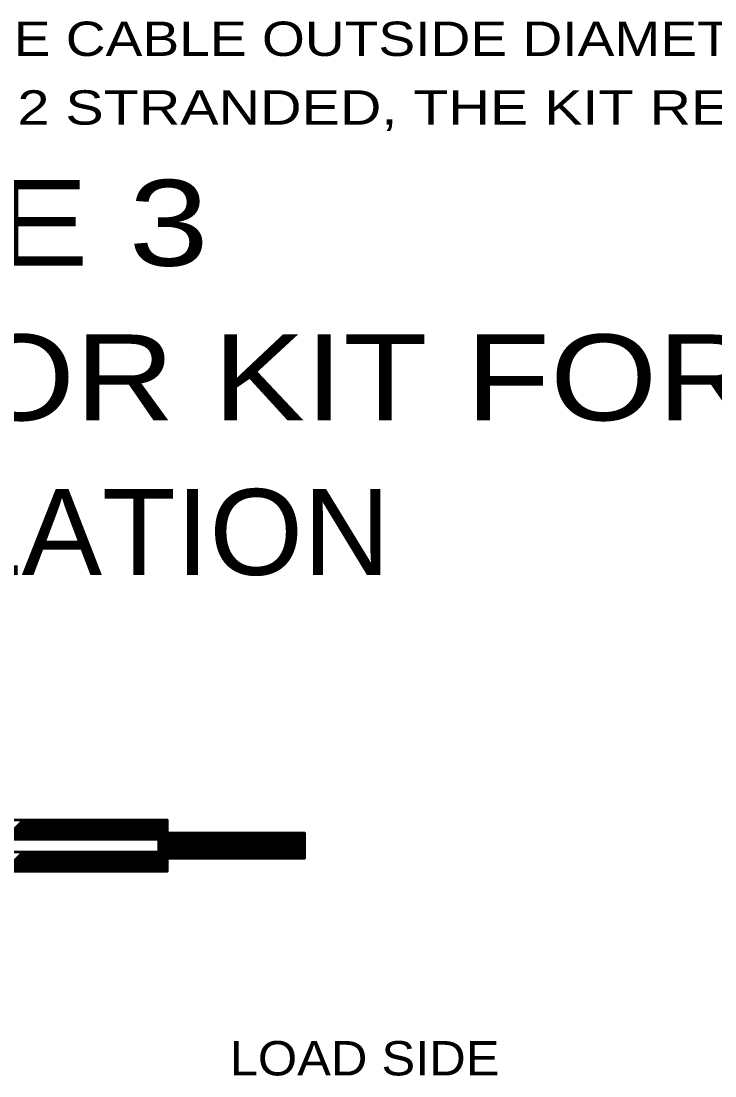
# Model space of a CAD drawing. Extents: x -32 to 824, y -6 to 538.
# Drawn here: x 656.1 to 704.6, y 268.2 to 341.9 of the extents above; entities that cross this region are included whole.
import ezdxf
from ezdxf.enums import TextEntityAlignment as Align

# ---------------------------------------------------------------- set-up
doc = ezdxf.new("R2010")
doc.units = 0
doc.header["$LTSCALE"] = 1.1
doc.layers.add('1', color=7, linetype='Continuous', lineweight=53)

msp = doc.modelspace()

# ---------------------------------------------------------------- linework, layer by layer
at = {"layer": '1'}
for p, q in [((654.939, 284.763), (656.289, 286.113)), ((655.109, 284.763), (656.459, 286.113)), ((655.279, 284.763), (656.629, 286.113)), ((655.448, 284.763), (656.798, 286.113)), ((655.618, 284.763), (656.968, 286.113)), ((655.788, 284.763), (657.138, 286.113)), ((655.957, 284.763), (657.307, 286.113)), ((656.127, 284.763), (657.477, 286.113)), ((656.297, 284.763), (657.647, 286.113)), ((656.466, 284.763), (657.817, 286.113)), ((656.636, 284.763), (657.986, 286.113)), ((656.806, 284.763), (658.156, 286.113)), ((656.976, 284.763), (658.326, 286.113)), ((657.145, 284.763), (658.495, 286.113)), ((657.315, 284.763), (658.665, 286.113)), ((657.485, 284.763), (658.835, 286.113)), ((657.654, 284.763), (659.004, 286.113)), ((657.824, 284.763), (659.174, 286.113)), ((657.994, 284.763), (659.344, 286.113)), ((658.163, 284.763), (659.514, 286.113)), ((658.333, 284.763), (659.683, 286.113)), ((658.503, 284.763), (659.853, 286.113)), ((658.673, 284.763), (660.023, 286.113)), ((658.842, 284.763), (660.192, 286.113)), ((659.012, 284.763), (660.362, 286.113)), ((659.182, 284.763), (660.532, 286.113)), ((659.351, 284.763), (660.702, 286.113)), ((659.521, 284.763), (660.871, 286.113)), ((659.691, 284.763), (661.041, 286.113)), ((659.861, 284.763), (661.211, 286.113)), ((660.03, 284.763), (661.38, 286.113)), ((660.2, 284.763), (661.55, 286.113)), ((660.37, 284.763), (661.72, 286.113)), ((660.539, 284.763), (661.889, 286.113)), ((660.709, 284.763), (662.059, 286.113)), ((660.879, 284.763), (662.229, 286.113)), ((661.048, 284.763), (662.399, 286.113)), ((661.218, 284.763), (662.568, 286.113)), ((661.388, 284.763), (662.738, 286.113)), ((661.558, 284.763), (662.908, 286.113)), ((661.727, 284.763), (663.077, 286.113)), ((661.897, 284.763), (663.247, 286.113)), ((662.067, 284.763), (663.417, 286.113)), ((662.236, 284.763), (663.587, 286.113)), ((662.406, 284.763), (663.756, 286.113)), ((662.576, 284.763), (663.926, 286.113)), ((662.746, 284.763), (664.096, 286.113)), ((662.915, 284.763), (664.265, 286.113)), ((663.085, 284.763), (664.435, 286.113)), ((663.255, 284.763), (664.605, 286.113)), ((663.424, 284.763), (664.774, 286.113)), ((663.594, 284.763), (664.944, 286.113)), ((663.764, 284.763), (665.114, 286.113)), ((663.933, 284.763), (665.284, 286.113)), ((664.103, 284.763), (665.453, 286.113)), ((664.273, 284.763), (665.623, 286.113)), ((664.443, 284.763), (665.793, 286.113)), ((664.612, 284.763), (665.962, 286.113)), ((664.782, 284.763), (666.132, 286.113)), ((664.952, 284.763), (666.302, 286.113)), ((665.122, 284.763), (666.32, 285.961)), ((665.291, 284.763), (666.32, 285.791)), ((665.461, 284.763), (666.32, 285.622)), ((665.631, 284.763), (666.32, 285.452)), ((665.72, 284.683), (666.32, 285.282)), ((665.72, 284.513), (666.32, 285.113)), ((665.72, 284.343), (666.32, 284.943)), ((665.72, 284.174), (666.32, 284.773)), ((665.72, 284.004), (666.32, 284.603)), ((666.32, 285.17), (666.363, 285.213)), ((666.32, 285), (666.533, 285.213)), ((666.32, 284.83), (666.702, 285.213)), ((666.32, 284.661), (666.872, 285.213)), ((666.32, 284.491), (667.042, 285.213)), ((666.32, 284.321), (667.211, 285.213)), ((666.32, 284.151), (667.381, 285.213)), ((666.32, 283.982), (667.551, 285.213)), ((666.32, 283.812), (667.721, 285.213)), ((666.32, 283.642), (667.89, 285.213)), ((666.32, 283.473), (668.06, 285.213)), ((668.054, 283.413), (666.32, 285.146)), ((667.884, 283.413), (666.32, 284.977)), ((667.714, 283.413), (666.32, 284.807)), ((667.545, 283.413), (666.32, 284.637)), ((668.223, 283.413), (666.423, 285.213)), ((666.43, 283.413), (668.23, 285.213)), ((668.393, 283.413), (666.593, 285.213)), ((666.599, 283.413), (668.399, 285.213)), ((668.563, 283.413), (666.763, 285.213)), ((666.769, 283.413), (668.569, 285.213)), ((668.732, 283.413), (666.932, 285.213)), ((666.939, 283.413), (668.739, 285.213)), ((668.902, 283.413), (667.102, 285.213)), ((667.109, 283.413), (668.909, 285.213)), ((669.072, 283.413), (667.272, 285.213)), ((667.278, 283.413), (669.078, 285.213)), ((669.242, 283.413), (667.442, 285.213)), ((667.448, 283.413), (669.248, 285.213)), ((669.411, 283.413), (667.611, 285.213)), ((667.618, 283.413), (669.418, 285.213)), ((669.581, 283.413), (667.781, 285.213)), ((667.787, 283.413), (669.587, 285.213)), ((669.751, 283.413), (667.951, 285.213)), ((667.957, 283.413), (669.757, 285.213)), ((669.92, 283.413), (668.12, 285.213)), ((668.127, 283.413), (669.927, 285.213)), ((670.09, 283.413), (668.29, 285.213)), ((668.296, 283.413), (670.096, 285.213)), ((670.26, 283.413), (668.46, 285.213)), ((668.466, 283.413), (670.266, 285.213)), ((670.43, 283.413), (668.63, 285.213)), ((668.636, 283.413), (670.436, 285.213)), ((670.599, 283.413), (668.799, 285.213)), ((668.806, 283.413), (670.606, 285.213)), ((670.769, 283.413), (668.969, 285.213)), ((668.975, 283.413), (670.775, 285.213)), ((670.939, 283.413), (669.139, 285.213)), ((669.145, 283.413), (670.945, 285.213)), ((671.108, 283.413), (669.308, 285.213)), ((669.315, 283.413), (671.115, 285.213)), ((671.278, 283.413), (669.478, 285.213)), ((669.484, 283.413), (671.284, 285.213)), ((671.448, 283.413), (669.648, 285.213)), ((669.654, 283.413), (671.454, 285.213)), ((671.617, 283.413), (669.817, 285.213)), ((669.824, 283.413), (671.624, 285.213)), ((671.787, 283.413), (669.987, 285.213)), ((669.994, 283.413), (671.793, 285.213)), ((671.957, 283.413), (670.157, 285.213)), ((670.163, 283.413), (671.963, 285.213)), ((672.127, 283.413), (670.327, 285.213)), ((670.333, 283.413), (672.133, 285.213)), ((672.296, 283.413), (670.496, 285.213)), ((670.503, 283.413), (672.303, 285.213)), ((672.466, 283.413), (670.666, 285.213)), ((670.672, 283.413), (672.472, 285.213)), ((672.636, 283.413), (670.836, 285.213)), ((670.842, 283.413), (672.642, 285.213)), ((672.805, 283.413), (671.005, 285.213)), ((671.012, 283.413), (672.812, 285.213)), ((672.975, 283.413), (671.175, 285.213)), ((671.181, 283.413), (672.981, 285.213)), ((673.145, 283.413), (671.345, 285.213)), ((671.351, 283.413), (673.151, 285.213)), ((673.315, 283.413), (671.514, 285.213)), ((671.521, 283.413), (673.321, 285.213)), ((673.484, 283.413), (671.684, 285.213)), ((671.691, 283.413), (673.49, 285.213)), ((673.654, 283.413), (671.854, 285.213)), ((671.86, 283.413), (673.66, 285.213)), ((673.824, 283.413), (672.024, 285.213)), ((672.03, 283.413), (673.83, 285.213)), ((673.993, 283.413), (672.193, 285.213)), ((672.2, 283.413), (674, 285.213)), ((674.163, 283.413), (672.363, 285.213)), ((672.369, 283.413), (674.169, 285.213)), ((674.333, 283.413), (672.533, 285.213)), ((672.539, 283.413), (674.339, 285.213)), ((674.502, 283.413), (672.702, 285.213)), ((672.709, 283.413), (674.509, 285.213)), ((674.672, 283.413), (672.872, 285.213)), ((672.879, 283.413), (674.678, 285.213)), ((674.842, 283.413), (673.042, 285.213)), ((673.048, 283.413), (674.848, 285.213)), ((675.012, 283.413), (673.212, 285.213)), ((673.218, 283.413), (675.018, 285.213)), ((675.181, 283.413), (673.381, 285.213)), ((673.388, 283.413), (675.188, 285.213)), ((675.351, 283.413), (673.551, 285.213)), ((673.557, 283.413), (675.357, 285.213)), ((675.521, 283.413), (673.721, 285.213)), ((673.727, 283.413), (675.527, 285.213)), ((675.69, 283.413), (673.89, 285.213)), ((673.897, 283.413), (675.697, 285.213)), ((675.86, 283.413), (674.06, 285.213)), ((674.066, 283.413), (675.866, 285.213)), ((675.92, 283.523), (674.23, 285.213)), ((674.236, 283.413), (675.92, 285.096)), ((675.92, 283.692), (674.399, 285.213)), ((674.406, 283.413), (675.92, 284.927)), ((675.92, 283.862), (674.569, 285.213)), ((674.576, 283.413), (675.92, 284.757)), ((675.92, 284.032), (674.739, 285.213)), ((674.745, 283.413), (675.92, 284.587)), ((675.92, 284.201), (674.909, 285.213)), ((675.92, 284.371), (675.078, 285.213)), ((675.92, 284.541), (675.248, 285.213)), ((675.92, 284.711), (675.418, 285.213)), ((675.92, 284.88), (675.587, 285.213)), ((675.92, 285.05), (675.757, 285.213)), ((654.895, 282.513), (656.245, 283.863)), ((655.065, 282.513), (656.415, 283.863)), ((655.235, 282.513), (656.585, 283.863)), ((655.404, 282.513), (656.754, 283.863)), ((655.574, 282.513), (656.924, 283.863)), ((655.744, 282.513), (657.094, 283.863)), ((655.913, 282.513), (657.264, 283.863)), ((656.083, 282.513), (657.433, 283.863)), ((656.253, 282.513), (657.603, 283.863)), ((656.423, 282.513), (657.773, 283.863)), ((656.592, 282.513), (657.942, 283.863)), ((656.762, 282.513), (658.112, 283.863)), ((656.932, 282.513), (658.282, 283.863)), ((657.101, 282.513), (658.452, 283.863)), ((657.271, 282.513), (658.621, 283.863)), ((657.441, 282.513), (658.791, 283.863)), ((657.611, 282.513), (658.961, 283.863)), ((657.78, 282.513), (659.13, 283.863)), ((657.95, 282.513), (659.3, 283.863)), ((658.12, 282.513), (659.47, 283.863)), ((658.289, 282.513), (659.639, 283.863)), ((658.459, 282.513), (659.809, 283.863)), ((658.629, 282.513), (659.979, 283.863)), ((658.798, 282.513), (660.149, 283.863)), ((658.968, 282.513), (660.318, 283.863)), ((659.138, 282.513), (660.488, 283.863)), ((659.308, 282.513), (660.658, 283.863)), ((659.477, 282.513), (660.827, 283.863)), ((659.647, 282.513), (660.997, 283.863)), ((659.817, 282.513), (661.167, 283.863)), ((659.986, 282.513), (661.337, 283.863)), ((660.156, 282.513), (661.506, 283.863)), ((660.326, 282.513), (661.676, 283.863)), ((660.496, 282.513), (661.846, 283.863)), ((660.665, 282.513), (662.015, 283.863)), ((660.835, 282.513), (662.185, 283.863)), ((661.005, 282.513), (662.355, 283.863)), ((661.174, 282.513), (662.524, 283.863)), ((661.344, 282.513), (662.694, 283.863)), ((661.514, 282.513), (662.864, 283.863)), ((661.683, 282.513), (663.034, 283.863)), ((661.853, 282.513), (663.203, 283.863)), ((662.023, 282.513), (663.373, 283.863)), ((662.193, 282.513), (663.543, 283.863)), ((662.362, 282.513), (663.712, 283.863)), ((662.532, 282.513), (663.882, 283.863)), ((662.702, 282.513), (664.052, 283.863)), ((662.872, 282.513), (664.221, 283.863)), ((663.041, 282.513), (664.391, 283.863)), ((663.211, 282.513), (664.561, 283.863)), ((663.381, 282.513), (664.731, 283.863)), ((663.55, 282.513), (664.9, 283.863)), ((663.72, 282.513), (665.07, 283.863)), ((663.89, 282.513), (665.24, 283.863)), ((664.059, 282.513), (665.409, 283.863)), ((664.229, 282.513), (665.579, 283.863)), ((664.399, 282.513), (666.32, 284.434)), ((664.569, 282.513), (666.32, 284.264)), ((664.738, 282.513), (666.32, 284.094)), ((664.908, 282.513), (666.32, 283.925)), ((667.375, 283.413), (666.32, 284.468)), ((667.205, 283.413), (666.32, 284.298)), ((667.035, 283.413), (666.32, 284.128)), ((666.866, 283.413), (666.32, 283.959)), ((666.696, 283.413), (666.32, 283.789)), ((674.915, 283.413), (675.92, 284.418)), ((675.085, 283.413), (675.92, 284.248)), ((675.254, 283.413), (675.92, 284.078)), ((675.424, 283.413), (675.92, 283.909)), ((665.078, 282.513), (666.32, 283.755)), ((665.247, 282.513), (666.32, 283.585)), ((665.417, 282.513), (666.32, 283.416)), ((665.587, 282.513), (666.32, 283.246)), ((665.757, 282.513), (666.32, 283.076)), ((666.526, 283.413), (666.32, 283.619)), ((666.356, 283.413), (666.32, 283.449)), ((675.594, 283.413), (675.92, 283.739)), ((675.764, 283.413), (675.92, 283.569)), ((665.926, 282.513), (666.32, 282.906)), ((666.096, 282.513), (666.32, 282.737)), ((666.266, 282.513), (666.32, 282.567))]:
    msp.add_line(p, q, dxfattribs=at)
for points in [[(630.031, 286.687), (630.031, 288.187), (633.32, 287.013), (645.32, 287.013), (645.92, 286.113), (654.32, 286.113), (666.32, 286.113), (666.32, 282.513), (654.32, 282.513), (645.92, 282.513), (645.32, 281.613), (633.32, 281.613), (630.031, 280.439), (630.031, 281.939)], [(642.931, 283.863), (642.931, 284.763), (665.72, 284.763), (665.72, 283.863)]]:
    msp.add_lwpolyline(points, close=True, dxfattribs=at)
for points in [[(666.32, 282.513), (666.32, 286.113), (666.32, 285.213)], [(666.32, 285.213), (675.92, 285.213), (675.92, 283.413), (666.32, 283.413)]]:
    msp.add_lwpolyline(points, dxfattribs=at)

# ---------------------------------------------------------------- texts
for s, width, p in [('X IS 43.23mm2 STRANDED, AND THE LOAD SIDE CABLE OUTSIDE DIAMETER Y', 1.2, (568.716, 339.495)), ('IS 7.4mm AND THE CONDUCTOR Z IS 3.29mm2 STRANDED, THE KIT REQUIRED', 1.25, (568.716, 334.695)), ('LOAD SIDE', 1.1, (670.692, 268.262))]:
    msp.add_text(s, height=2.4, dxfattribs=dict(at, width=width)).set_placement(p)
for s, width, p in [('TYPE 3', 1.25, (651.939, 324.834)), ('UNFUSED "Y" CONNECTOR KIT FOR POLE BASE', 1.2, (651.939, 314.034)), ('INSTALLATION', 1.05, (651.939, 303.234))]:
    msp.add_text(s, height=6, dxfattribs=dict(at, width=width)).set_placement(p, align=Align.CENTER)

doc.saveas('drawing.dxf')
